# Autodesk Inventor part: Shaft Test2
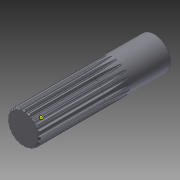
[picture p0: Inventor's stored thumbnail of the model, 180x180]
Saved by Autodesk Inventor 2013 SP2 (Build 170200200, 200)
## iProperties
Created: 2020-02
Part Number: Shaft Test2
Material: Steel
Document SubType Name: Modeling
Designer: DELL
Density: 1 g/cm^3
CustomPartVersion: 1
Author: DELL
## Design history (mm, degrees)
sketch "Sketch3"
  geometry: C1 r 2.5 at (0, 0); 1 further point
  constraints: 1 centre point, 1 coincident
  dimensions: "d16" = 5 diameter of C1
extrude "Extrusion1" new body sketch "Sketch3" distance "d18" = 20; taper "d19" = 0 deg
chamfer "Chamfer4" distance "d21" = 0.25; stored, may be unused: second distance "d22" = 2, angle "d23" = 45 deg
node "Involute Splining8"
sketch "Sketch4" dims "d21" = 0.25, "d22" = 2
  geometry: L1 (0, 0)-(1.12, 2.704); L2 (0, -3.533)-(0, 3.875) reference; L3 (0, 0)-(-1.12, 2.704); L4 (0.643, 1.552)-(-1.571, 2.469); C1 r 2.375 at (0, 0); C2 r 2.475 at (0, 0); C3 r 2.183 at (0, 0); C4 r 1.68 at (0, 0); 1 further point
  constraints: 6 end point, 4 centre point, 4 coincident, 1 perpendicular, 1 point on line, 1 tangent
  dimensions: "d46" = 4.75 diameter of C1; "d48" = 4.95 diameter of C2; "d49" = 4.367 diameter of C3; "d50" = 3.359 diameter of C4; "d52" = 22.5 deg angle of L1 L2; "d53" = 45 deg angle of L1 L3
body "Solid2"
feature "Shaft Groove"
